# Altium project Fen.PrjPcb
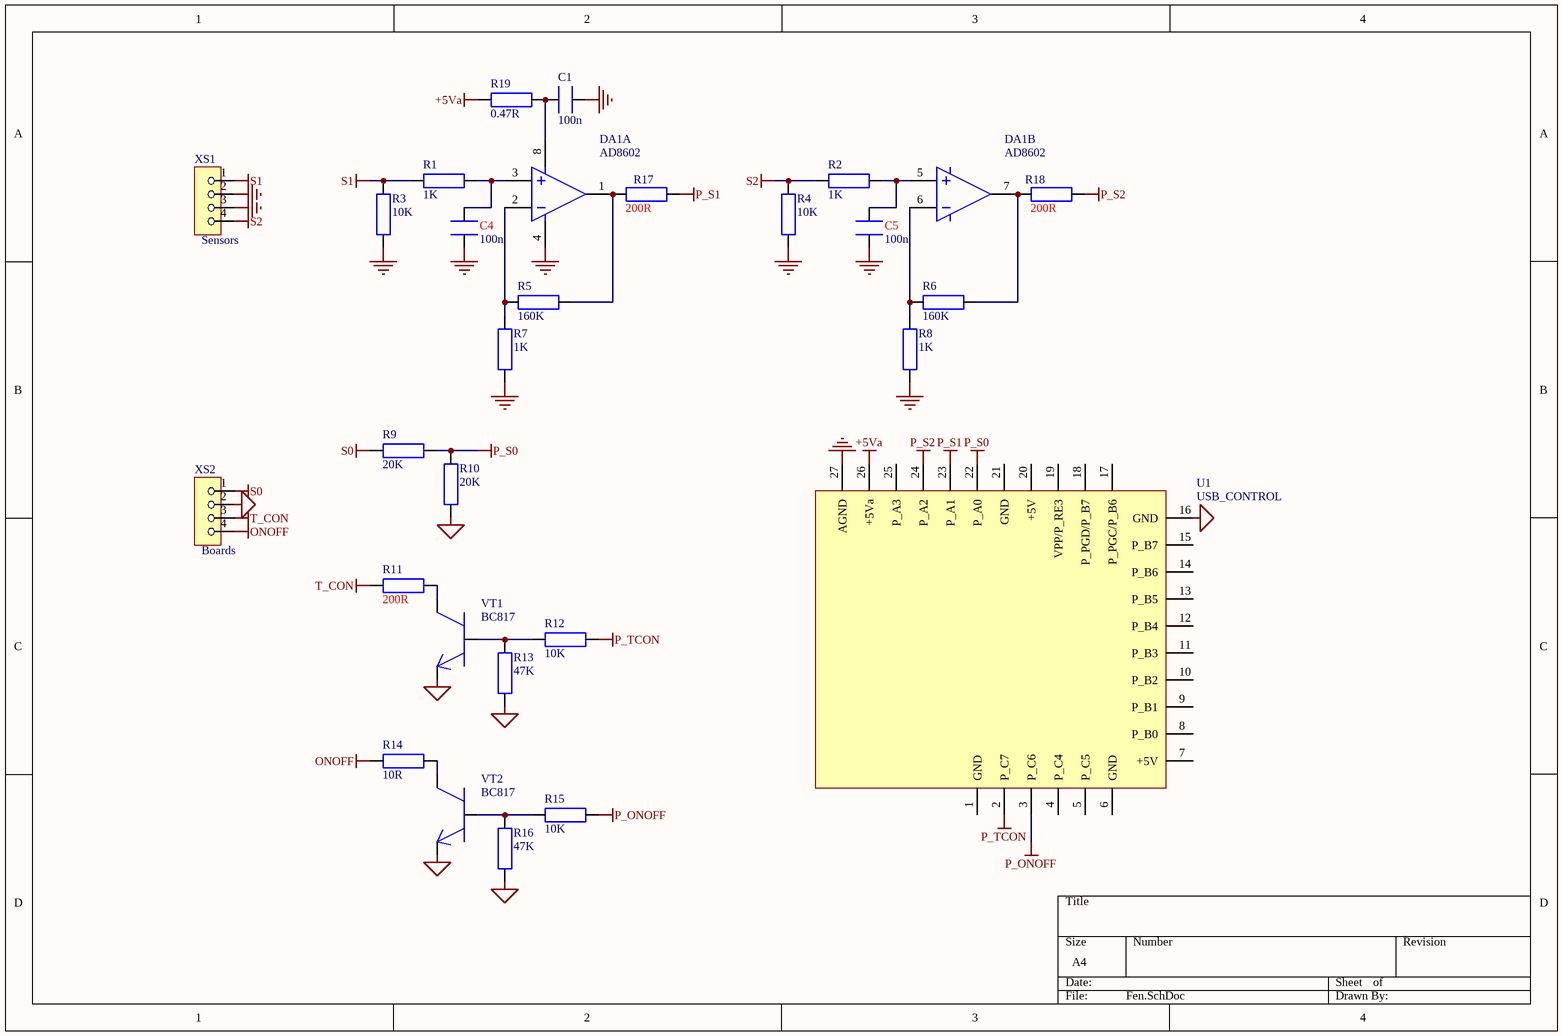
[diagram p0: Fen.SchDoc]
1 sheet, 28 parts. Net scope: global (net labels, ports and power ports of the same name join across sheets).
Board file: Fen.PcbDoc

## Sheet Fen.SchDoc
size A4

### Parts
C1  100n  [0805]
C4  100n  [0805]
C5  100n  [0805]
DA1  AD8602  [SO-8]  (parts A,B of 2)
R1  1K  [0805]
R2  1K  [0805]
R3  10K  [0805]
R4  10K  [0805]
R5  160K  [0805]
R6  160K  [0805]
R7  1K  [0805]
R8  1K  [0805]
R9  20K  [0805]
R10  20K  [0805]
R11  200R  [0805]
R12  10K  [0805]
R13  47K  [0805]
R14  10R  [0805]
R15  10K  [0805]
R16  47K  [0805]
R17  200R  [0805]
R18  200R  [0805]
R19  0.47R  [1206]
U1  USB_CONTROL  [F_FTDI_CONTROL]
VT1  BC817  [SOT-23]
VT2  BC817  [SOT-23]
XS1  Sensors  [F_OWF-4]
XS2  Boards  [F_OWF-4]

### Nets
+5Va: R19.1 U1.26(+5Va)
DGND: R10.1 R13.1 R16.1 U1.16(GND) VT1.2 VT2.2 XS2.2
GND: C1.2 C4.2 C5.2 DA1.4 R3.1 R4.1 R7.1 R8.1 U1.27(AGND) XS1.2 XS1.3
ONOFF: R14.2 XS2.4
P_ONOFF: R15.1 U1.3(P_C6)
P_S0: R9.2 R10.2 U1.22(P_A0)
P_S1: R17.2 U1.23(P_A1)
P_S2: R18.2 U1.24(P_A2)
P_TCON: R12.1 U1.2(P_C7)
S0: R9.1 XS2.1
S1: R1.1 R3.2 XS1.1
S2: R2.1 R4.2 XS1.4
T_CON: R11.2 XS2.3
NetC1_1: C1.1 DA1.8 R19.2
NetC4_1: C4.1 DA1.3 R1.2
NetC5_1: C5.1 DA1.5 R2.2
NetDA1_1: DA1.1 R5.2 R17.1
NetDA1_2: DA1.2 R5.1 R7.2
NetDA1_6: DA1.6 R6.1 R8.2
NetDA1_7: DA1.7 R6.2 R18.1
NetR11_1: R11.1 VT1.3
NetR12_2: R12.2 R13.2 VT1.1
NetR14_1: R14.1 VT2.3
NetR15_2: R15.2 R16.2 VT2.1

Not connected (* = marked no-connect by the designer): U1 1(GND) 4(P_C4) 5(P_C5) 6(GND) 7(+5V) 8(P_B0) 9(P_B1) 10(P_B2) 11(P_B3) 12(P_B4) 13(P_B5) 14(P_B6) 15(P_B7) 17(P_PGC/P_B6) 18(P_PGD/P_B7) 19(VPP/P_RE3) 20(+5V) 21(GND) 25(P_A3)

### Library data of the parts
C1 C4 C5 = C
DA1 = LM393: Сдвоенный компаратор
R1-R19 = R
U1 = USB_CONTROL: PIC с FTDI232
XS1 XS2 = CONN_4: ТЕЛЕВИЗИОННЫЙ РАЗЪЕМ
